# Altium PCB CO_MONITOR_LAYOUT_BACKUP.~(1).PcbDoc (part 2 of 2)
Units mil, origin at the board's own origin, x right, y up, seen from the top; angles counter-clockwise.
Board outline 3010 x 4260 mil, 2 copper layers (Top Layer, Bottom Layer), stack 62 mil thick; 120 components, 0 nets, 435 pads, 123 vias.
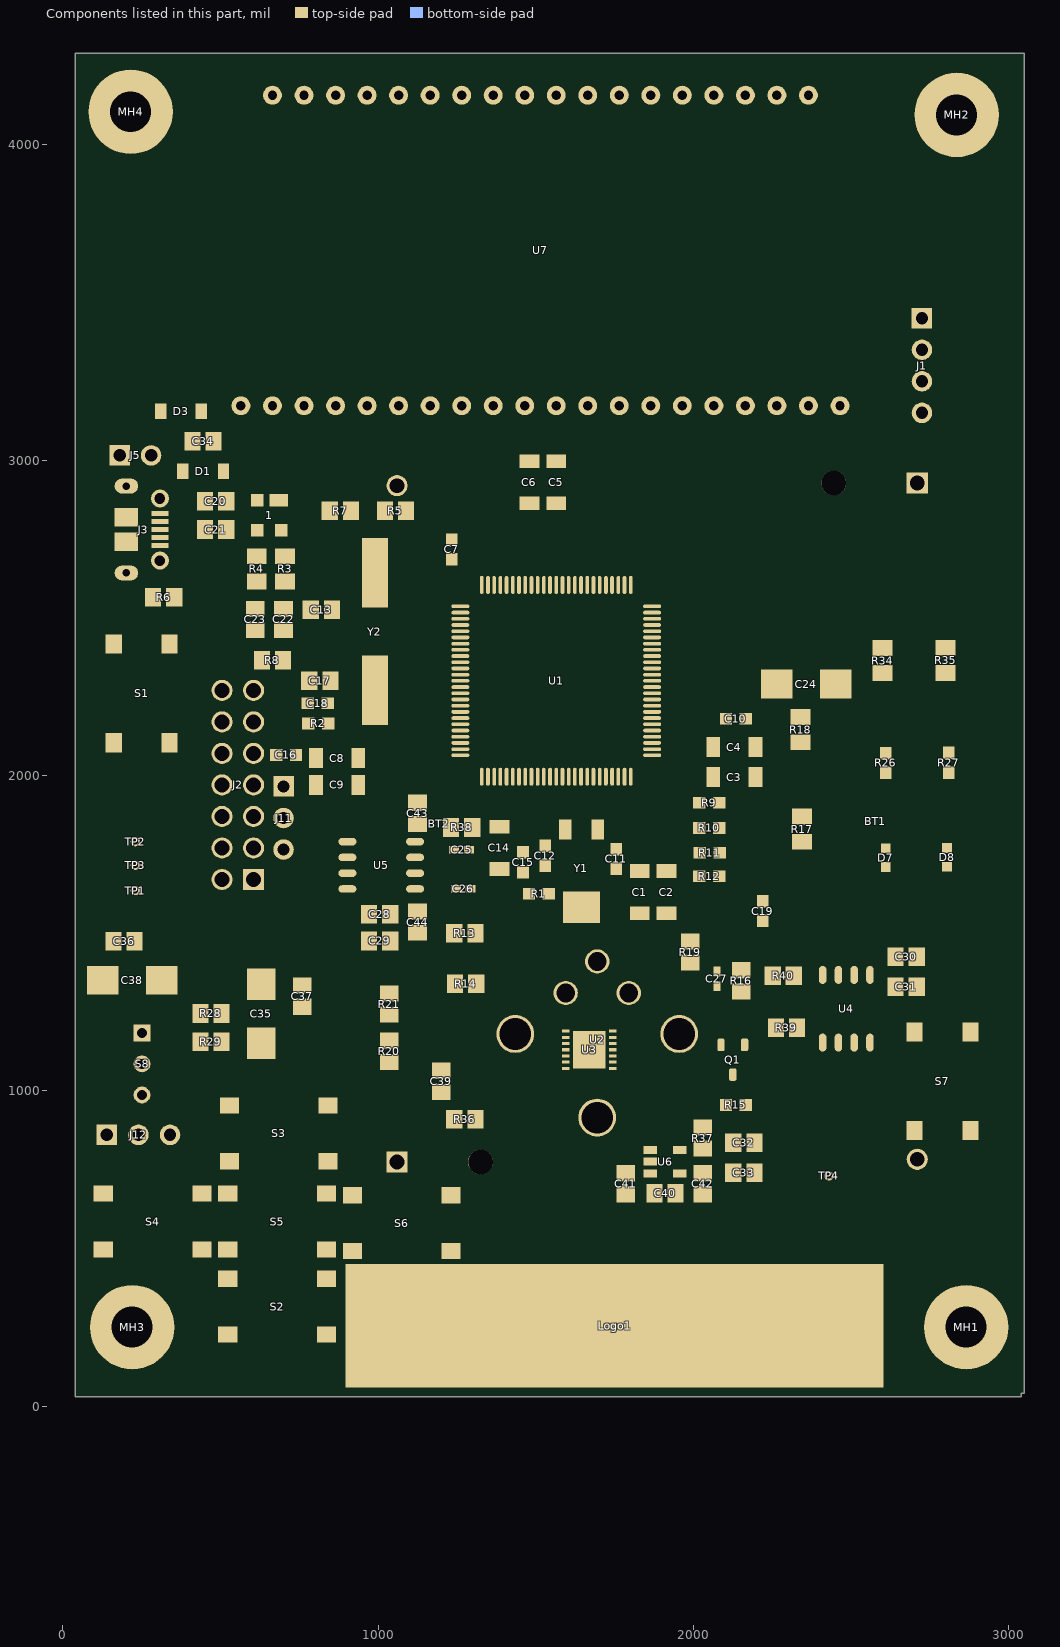
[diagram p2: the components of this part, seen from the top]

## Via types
v1: diameter 50, hole 28, Top Layer to Bottom Layer, 65 vias
v2: diameter 50, hole 28, Top Layer to Bottom Layer, tented top, 29 vias
v3: diameter 39.37, hole 19.68, Top Layer to Bottom Layer, 24 vias
v4: diameter 19.68, hole 7.87, Top Layer to Bottom Layer, tented top, 5 vias

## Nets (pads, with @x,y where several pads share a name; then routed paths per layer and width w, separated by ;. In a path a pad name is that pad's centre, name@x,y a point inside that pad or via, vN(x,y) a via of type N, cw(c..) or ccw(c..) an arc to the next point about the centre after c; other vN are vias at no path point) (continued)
copper on no net: | length 172556.5
  Top Layer w10: 105.3,4154.7 v3(128.91,4154.7) v3(301.09,4154.7) v3(301.09,4055.3) v3(128.91,4055.3) ; v3(133.91,200.3) v3(306.09,200.3) v3(306.09,299.7) v3(133.91,299.7) ; 161.42,2103.5 161.42,2416.5 226.5,2416.5 280,2470 v2(500,2470) ; v1(220,3210) 315,3210 375,3150 429.47,3150 439.47,3140 465,3140 480,3125 480,3061.54 478.46,3060 ; 227.65,1474.68 295.32,1474.68 315,1455 315,1205 293.43,1183.43 251.18,1183.43 ; 230,1477.03 230,1565 ; 230,1635 230,1565 ; 230,1790 325,1790 375,1740 375,1590 455,1510 740,1510 840,1410 840,1328.46 ; 280,3015 330,3015 355.8,3040.8 355.8,3124.2 340,3140 310.53,3140 ; 286.54,2565 279.06,2565 201.85,2642.2 ; 308.15,2681.57 296.57,2681.57 257.2,2642.2 201.85,2642.2 ; 308.15,2780 355,2780 439.44,2695.56 535,2695.56 617.2,2777.76 617.2,2697.2 615,2695 ; 308.15,2805.59 308.74,2805 355,2805 450,2710 525,2710 580,2765 580,2860 592.24,2872.24 617.2,2872.24 617.2,2842.2 655,2804.4 655,2760 680,2735 680,2700 ; 308.15,2831.18 361.18,2831.18 380.53,2850.53 380.53,2965 ; 308.15,2878.43 241.22,2878.43 201.85,2917.8 201.85,2819.37 201.85,2740.63 201.85,2642.2 ; 338.58,2103.5 338.58,2416.5 493.5,2416.5 545,2365 631.54,2365 ; 436.54,1245 436.54,1445 ; 441.5,496.42 373.58,496.42 295,575 295,685 470,860 1145,860 1160,845 1485,845 1575,755 1575,630 1610,595 2800,595 2950,745 2950,2795 2910,2835 2340,2835 2245,2740 2245,2525 2215,2495 2160,2495 2004.37,2339.37 1869.13,2339.37 ; 446.54,2870 451.54,2865 451.54,2780 ; 503.46,1245 503.46,1323.46 517.68,1337.68 629.65,1337.68 755.78,1337.68 ; 505,1770 515,1770 565,1820 645,1820 695,1770 ; 505,1970 560,1915 965,1915 980,1930 980,2010 1090,2120 1090,2185 1145.94,2240.94 1260.87,2240.94 ; 509.47,2965 509.47,2874 513.46,2870 513.46,2785 518.46,2780 555,2780 565,2790 565,2915 630,2980 745,2980 780,2945 780,2795 762.76,2777.76 692.8,2777.76 692.8,2747.2 710,2730 810,2730 870,2790 1075,2790 1110,2755 1110,2485 1137.52,2457.48 1260.87,2457.48 ; 523.5,403.58 648.58,403.58 705,460 705,505 765,565 1435,565 1485,515 2780,515 2995,730 2995,2810 2815,2990 2435,2990 2200,2755 2200,2570 2185,2555 2145,2555 1988.43,2398.43 1869.13,2398.43 ; 523.5,496.42 523.5,558.1 665,699.6 665,740 765,840 1125,840 1135,830 1480,830 1560,750 1560,610 1590,580 2805,580 2965,740 2965,2800 2915,2850 2335,2850 2230,2745 2230,2535 2210,2515 2155,2515 1999.06,2359.06 1869.13,2359.06 ; v1(525,1445) 436.54,1445 ; 565,3172.5 565,3085 600,3050 745,3050 780,3015 1085,3015 1150,2950 1255,2950 1275,2930 1275,2750 1328.78,2696.22 1328.78,2604.13 ; 605,1670 605,1610 630,1585 770,1585 795,1610 795,1865 825,1895 970,1895 1000,1925 1000,2005 1105,2110 1105,2175 1151.26,2221.26 1260.87,2221.26 ; 605,1770 550,1715 550,1605 585,1570 780,1570 810,1600 810,1855 835,1880 980,1880 1020,1920 1020,2000 1120,2100 1120,2165 1156.57,2201.57 1260.87,2201.57 ; 605,1870 585,1870 535,1820 480,1820 455,1795 455,1575 475,1555 790,1555 825,1590 825,1845 845,1865 990,1865 1040,1915 1040,1995 1135,2090 1135,2155 1161.89,2181.89 1260.87,2181.89 ; 605,1970 555,2020 475,2020 440,1985 440,1570 470,1540 800,1540 840,1580 840,1835 855,1850 1000,1850 1060,1910 1060,1990 1150,2080 1150,2145 1167.2,2162.2 1260.87,2162.2 ; 605,2170 675,2170 725,2120 870,2120 v1(905,2155) ; 615,2615 615,2533.46 613.46,2535 433.46,2535 388.46,2490 175,2490 110,2555 110,3175 220,3285 450,3285 500,3235 500,3165 542.5,3122.5 542.5,3072.5 620,2995 911.93,2995 ; 665,3172.5 665,3100 690,3075 755,3075 795,3035 1095,3035 1160,2970 1285,2970 1295,2960 1295,2760 1348.46,2706.54 1348.46,2604.13 ; 684.92,2872.24 684.92,2929.92 v2(685,2930) ; 690,2615 690,2538.46 700,2528.46 700,2535 760,2595 v2(800,2595) ; 695,1760 695,1770 ; 698.46,2365 775,2365 v2(820,2410) ; 700,1765 695,1770 ; 739.68,2065 739.68,2089.1 755.58,2105 1025,2105 1060,2140 1060,2225 1174.37,2339.37 1260.87,2339.37 ; 765,1328.46 840,1328.46 ; 765,3172.5 765,3095 805,3055 1105,3055 1170,2990 1305,2990 1315,2980 1315,2770 1368.15,2716.85 1368.15,2604.13 ; 776.54,2285 781.54,2280 ; v2(790,2665) 895,2770 1045,2770 1075,2740 1075,2485 1122.2,2437.8 1260.87,2437.8 ; 841.5,776.42 943.58,776.42 965,755 965,690 1010,645 1110,645 1130,625 1520,625 1580,565 2810,565 2980,735 2980,2805 2920,2865 2330,2865 2215,2750 2215,2545 2205,2535 2150,2535 1993.74,2378.74 1869.13,2378.74 ; 841.5,2120 841.5,2165 841.5,2228.83 ; 846.54,2840 846.54,2918.46 v2(840,2925) v2@860,2925 ; 848.46,2280 851.46,2282.99 1000,2282.99 1082.99,2282.99 1159.06,2359.06 1260.87,2359.06 ; 863.46,2525 915,2525 920,2530 920,2642.01 935,2657.01 1000,2657.01 ; 865,3172.5 865,3115 905,3075 1115,3075 1180,3010 1325,3010 1335,3000 1335,2780 1387.83,2727.17 1387.83,2604.13 ; v1(870,1970) 936.93,1970 936.93,2055 1000,2055 1075,2130 1075,2195 1160.31,2280.31 1260.87,2280.31 ; 902.72,1640 860,1640 855,1635 855,1590 885,1560 971.54,1560 971.54,1475 971.54,1385 915,1328.46 890,1328.46 ; 965,3172.5 965,3120 990,3095 1125,3095 1190,3030 1345,3030 1355,3020 1355,2790 1407.52,2737.48 1407.52,2604.13 ; v1@990,1780 v1(985,1780) 985,1810 1088.46,1913.46 1110,1913.46 ; 1000,2665 1000,2445 1066.26,2378.74 1260.87,2378.74 ; 1021.54,2840 913.46,2840 913.46,2995 1075,2995 1165,2905 1165,2650 1195,2620 1195,2535 1213.46,2516.54 1260.87,2516.54 ; 1035,1091.54 1035,922.13 ; 1035,1158.46 1035,1200 ; 1035,1241.54 1035,1200 ; 1038.46,1475 1038.46,1560 ; v1(1065,2435) 1081.89,2418.11 1260.87,2418.11 ; 1065,3172.5 1065,3135 1085,3115 1135,3115 1200,3050 1365,3050 1375,3040 1375,2800 1427.2,2747.8 1427.2,2604.13 ; 1088.46,2840 1135,2840 1145,2830 v1(1145,2590) 1180,2555 1180,2525 1208.15,2496.85 1260.87,2496.85 ; 1117.28,1640 1246.38,1640 ; 1117.28,1690 1205,1690 1241.38,1726.38 1241.38,1765 ; 1125,1913.46 1110,1913.46 ; v1(1145,2520) 1145,2490 1157.83,2477.17 1260.87,2477.17 ; v1(1165,1260) 1165,1300 1204.65,1339.65 1244.28,1339.65 ; 1165,3172.5 1165,3115 1210,3070 1385,3070 1395,3060 1395,2810 1446.89,2758.11 1446.89,2604.13 ; v1@1180,1375 v1(1180.22,1374.78) ; v1(1185,2125) 1202.52,2142.52 1260.87,2142.52 ; v2@1196.38,1735 v2(1190,1735) 1220,1705 ; 1200,996.54 1238.46,996.54 1246.73,988.27 ; 1200,1063.46 1255,1063.46 ; 1221.5,496.42 2781.42,496.42 3010,725 3010,2835 2840,3005 2430,3005 2185,2760 2185,2590 2167.5,2572.5 2137.5,2572.5 1983.11,2418.11 1869.13,2418.11 ; v2(1225,1415) 1195,1445 1195,1570 1246.38,1621.38 1246.38,1640 ; 1231.54,1835 1231.54,1886.54 1248.46,1903.46 1265,1903.46 1298.46,1903.46 1328.78,1933.78 1328.78,1995.87 ; v1(1235,2610) 1235,2685.44 ; 1241.54,910 1255,923.46 1255,980 1246.73,988.27 ; 1260.87,2063.78 1193.78,2063.78 1180,2050 1180,1775 1145,1740 1117.28,1740 1027.41,1740 1005,1717.59 1005,1645 1020,1630 1065,1630 1085,1610 1115,1610 1125,1600 1125,1568.46 1166.54,1568.46 1174.8,1560.2 1174.8,1419.8 1105,1350 v1(1105,1200) 1035,1200 ; 1260.87,2083.46 1183.46,2083.46 1160,2060 1160,1995 1125,1995 1110,1980 1110,1913.46 ; 1260.87,2122.83 1357.83,2122.83 1405,2170 v1@1632.18,2170 ; 1260.87,2319.68 1309.68,2319.68 v1(1350,2360) ; 1260.87,2398.43 1483.72,2398.43 1735,2147.15 1735,2065 1710,2040 1565,2040 1565,1995.87 1565,1885 v2(1535,1855) ; 1265,3172.5 1265,3120 1295,3090 1395,3090 1415,3070 1415,2820 1466.57,2768.43 1466.57,2604.13 ; v1(1280,1015) 1253.27,988.27 1246.73,988.27 ; 1293.62,1640 1293.62,1618.62 1241.54,1566.54 1241.54,1500 1241.54,1449.05 1311.21,1379.37 1311.21,1339.65 ; 1298.46,1835 1288.62,1825.16 1288.62,1765 1288.62,1728.62 1246.38,1686.38 1246.38,1640 ; v2(1300,1690) 1341.81,1690 ; 1308.46,910 1325,926.54 1325,1035 1296.54,1063.46 1255,1063.46 ; 1308.46,1500 1308.46,1563.46 1341.81,1596.81 1341.81,1690 ; v2(1320,1215) 1355,1180 1435,1180 1435,1105 1490,1050 ; v2(1332.13,1432.13) 1437.87,1432.13 1500,1370 1569.42,1370 1599.42,1400 v1(1605,1400) 1605,1437.32 1632.68,1465 1789.67,1465 1955,1299.67 1955,1180 ; 1348.46,1995.87 1348.46,1931.65 1341.81,1925 1341.81,1690 ; 1365,3172.5 1365,3150 1435,3080 1435,2821.96 1486.26,2770.7 1486.26,2604.13 ; 1385,1836.93 1456.93,1836.93 ; 1407.52,1995.87 1407.52,2052.52 1485,2130 v1(1580,2130) ; v2(1427.2,1922.2) 1427.2,1995.87 ; 1460,1756.5 1460,1895 1486.26,1921.26 1486.26,1995.87 ; 1465,3172.5 1625,3012.5 1625,2835 1584.68,2794.69 1584.68,2604.13 ; v1(1470,1515) 1492.13,1492.87 1763.31,1492.87 1763.9,1493.46 1870,1493.46 1885,1478.46 1985,1478.46 ; v1@1480,2920 1480,2863.07 1565,2863.07 1545.31,2843.39 1545.31,2604.13 ; v1(1480,3085) 1480,2996.93 1565,2996.93 ; v1(1500,1095) 1534.68,1095 1550,1110.32 1595.2,1110.32 ; 1505.94,2604.13 1505.94,2504.06 v1(1740,2270) ; v1(1510,1285) 1510,1235 1530,1215 1530,1184.94 1565.26,1149.68 1595.2,1149.68 ; 1525,1776.5 1581.5,1776.5 1593.82,1788.82 1593.82,1828.03 1593.82,1896.18 1585,1905 1585,1995.55 1584.68,1995.87 ; 1525.63,2604.13 1525.63,2544.37 1775,2295 v1(1775,2190) ; 1541.5,1625 1541.5,1653.5 1524.85,1670.15 1504.85,1670.15 1500,1675 1500,1880 1545.31,1925.31 1545.31,1995.87 ; 1565,3172.5 1645,3092.5 1645,2830 1604.37,2789.37 1604.37,2604.13 ; v1(1580,980) 1580,945 1605,920 1645,920 ; 1595.2,1070.94 1575.94,1070.94 1565,1060 1565,1045 1572.21,1037.79 1657.59,1037.79 v1(1667.79,1027.59) ; 1595.2,1090.63 1565.63,1090.63 1525,1050 1490,1050 ; 1595.2,1130 1560.43,1130 1515,1175.43 1515,1205 1450,1270 1295,1270 1265,1240 1265,1160.15 1615.15,810 1735,810 1810,885 1880,885 1950,955 2040,955 2080,915 2080,825 2071.54,816.54 2030,816.54 2030,738.46 ; 1595.2,1169.37 1567.91,1169.37 1545,1192.28 1545,1305 1529.61,1320.39 1529.23,1320 1415,1320 1385,1290 1285,1290 1230,1235 1230,1150 1255,1125 1255,1063.46 ; 1595.2,1189.06 1570,1189.06 1560,1199.06 1560,1240 1582.13,1262.13 1647.13,1262.13 v1(1790,1405) ; 1604.37,1995.87 1604.37,1935.63 1630,1910 1660,1910 1696.18,1873.82 1696.18,1828.03 1696.18,1778.82 1708.5,1766.5 1770,1766.5 ; 1624.06,1995.87 1624.06,1945.94 1640,1930 1695,1930 1830,1795 1830,1695 1905,1695 1920,1680 ; 1624.06,2604.13 1624.06,2779.06 1665,2820 1665,3172.5 ; v1(1632.18,2095) v1(1632.18,2168.51) ; 1643.74,1995.87 1643.74,1956.26 1655,1945 1710,1945 1860,1795 1925,1795 1980,1740 1980,1650 2003.69,1626.31 2133.69,1626.31 2158.5,1601.5 2220,1601.5 ; 1643.74,2604.13 1643.74,2768.74 1685,2810 1685,3030 1765,3110 1765,3172.5 ; 1663.43,2604.13 1663.43,2758.43 1705,2800 1705,3005 1735,3035 1790,3035 1865,3110 1865,3172.5 ; 1683.11,2604.13 1683.11,2748.11 1725,2790 1725,2995 1745,3015 1870,3015 1965,3110 1965,3172.5 ; 1685,915 1870,915 2087.6,1132.6 2087.6,1145.71 2087.6,1177.6 2110,1200 2110,1230 1990,1350 1990,1406.54 ; v2(1695,1700) 1695,1703.5 1755,1703.5 ; 1702.8,2604.13 1702.8,2737.8 1745,2780 1745,2975 1765,2995 1945,2995 2065,3115 2065,3172.5 ; 1722.48,2604.13 1722.48,2727.48 1765,2770 1765,2955 1785,2975 2025,2975 2165,3115 2165,3172.5 ; 1742.17,1995.87 1742.17,1947.83 1815,1875 1945,1875 1955,1865 1955,1787.15 1987.15,1755 2020,1755 2020,1730 2030,1720 2070,1720 2081.5,1708.5 2081.5,1680 ; 1742.17,2604.13 1742.17,2717.17 1785,2760 1785,2940 1800,2955 2105,2955 2265,3115 2265,3172.5 ; 1744.8,1070.94 1810,1070.94 1840,1040.94 v1(1840,1030) ; 1744.8,1090.63 1879.37,1090.63 1895,1075 v1(1935,1075) ; 1744.8,1110.32 2010.32,1110.32 2055,1155 v1(2055,1215) ; 1744.8,1130 1790,1130 1825,1165 1825,1245 1855,1275 v1(1895,1275) ; 1744.8,1169.37 1784.37,1169.37 1790,1175 1790,1220 1775,1235 v2(1780,1235) ; 1761.85,2604.13 1761.85,2706.85 1805,2750 1805,2925 1815,2935 2185,2935 2365,3115 2365,3172.5 ; v1(1780,970) 1765,985 1645,985 1615,1015 1525,1015 1490,1050 ; 1781.54,1995.87 1781.54,1948.46 1835,1895 1955,1895 1975,1875 1975,1805 1985,1795 2082.99,1795 ; 1781.54,2604.13 1781.54,2696.54 1825,2740 1825,2900 1840,2915 2260,2915 2465,3120 2465,3172.5 ; 1795,671.54 1798.46,675 ; 1795,738.46 1795,795 1812.4,812.4 1862.76,812.4 ; 1801.22,1995.87 1801.22,1953.78 1841.5,1913.5 2018.5,1913.5 2018.5,1833.5 ; 1801.22,2604.13 1801.22,2696.22 v1(1877.5,2772.5) ; v1(1860,2595) 1860,2630 1855,2635 1880,2660 v1(1990,2660) ; 1862.76,737.6 1957.24,737.6 1957.24,688.78 1943.46,675 1945,610 ; 1869.13,2063.78 1988.78,2063.78 2015,2090 2063.07,2090 2063.07,1995 v2(1970,1995) ; 1869.13,2103.15 1870.98,2105 1990,2105 2065,2180 2103.5,2180 ; 1869.13,2122.83 1982.83,2122.83 2150,2290 2264.8,2290 2264.8,2199.8 2245,2180 2245,1925 2233.5,1913.5 2081.5,1913.5 ; 1869.13,2142.52 1982.52,2142.52 2205,2365 2460,2365 2490,2395 2490,2585 2590,2685 v1(2590,2750) ; 1869.13,2162.2 1982.2,2162.2 2200,2380 2390,2380 2459.23,2449.23 v1(2459.23,2750) ; 1869.13,2181.89 1981.89,2181.89 2195,2395 2355,2395 2405,2445 v1(2405,2710) ; 1869.13,2201.57 1981.57,2201.57 2190,2410 2295,2410 2345,2460 v1(2345,2685) ; 1869.13,2221.26 1981.26,2221.26 2190,2430 2275,2430 2290,2445 2290,2725 2355,2790 2635,2790 2665,2760 2665,2690 2600,2625 2600,2404.53 ; 1869.13,2240.94 1975.94,2240.94 2180,2445 2260,2445 2275,2460 2275,2730 2350,2805 2740,2805 2800,2745 2800,2405 ; 1869.13,2300 1925,2300 v1(1950,2275) ; 1869.13,2319.68 2009.68,2319.68 2165,2475 2215,2475 2260,2520 2260,2735 2345,2820 2905,2820 2935,2790 2935,1475 2885,1425 ; 1869.13,2437.8 1977.8,2437.8 2135,2595 2155,2595 2170,2610 2170,2770 2220,2820 v1(2220,2875) ; 1869.13,2457.48 1967.48,2457.48 2120,2610 2135,2610 2150,2625 2150,2780 2165,2795 v1(2165,2835) ; 1869.13,2477.17 1962.17,2477.17 2130,2645 2130,2785 2110,2805 v1(2110,2875) ; 1869.13,2496.85 1956.85,2496.85 2115,2655 2115,2775 2060,2830 v1(2060,2835) ; 1869.13,2516.54 1946.54,2516.54 2085,2655 2085,2745 2060,2770 v1(2010,2770) ; 1869.13,2536.22 1936.22,2536.22 2055,2655 2055,2710 2035,2730 1985,2730 v1(1945,2770) ; 1915,1696.93 1915,1675 1985,1605 2125,1605 2180,1550 2180,1520 2200,1500 2410,1500 ; 1957.24,812.4 1957.24,867.24 1973.46,883.46 2025,883.46 ; 1990,1473.46 2051.54,1473.46 2070,1455 2070,1435 2040,1405 2040,1340 2048.62,1331.38 2074.84,1331.38 2135.16,1331.38 2151.5,1315.04 2151.5,1263.5 2190,1225 2190,1110 2240,1060 2440,1060 2460,1080 2460,1152.72 ; 1995,1406.54 1995,1426.54 ; v1(1995,1550) 2030,1550 2115,1465 2270,1465 2318.46,1416.54 2318.46,1365 ; v2(2060,1050) 2061.22,1051.22 2125,1051.22 ; 2074.84,1378.62 2148.15,1378.62 ; 2081.5,1833.5 2082.99,1832.01 2082.99,1795 ; 2082.99,1755 2082.99,1795 ; 2101.54,955 2101.54,971.97 ; 2103.5,955 2103.5,911.5 2126.54,888.46 2126.54,835 2126.54,740 2126.54,611.54 2125,610 ; v2(2115,1560) 2115,1515 2150,1480 2360,1480 2380,1460 2380,1315 2328.46,1263.46 2328.46,1200 ; v2(2145,1720) v2(2205,1780) ; 2151.5,970 2162.4,980.91 2162.4,1145.71 ; 2151.5,1381.97 2168.46,1365 2251.54,1365 ; 2220,1538.5 2293.5,1538.5 v2(2295,1540) ; 2256.54,1195 2256.54,1128.46 2300,1085 2390,1085 2410,1105 2410,1152.72 ; 2261.54,1200 2261.54,1355 ; v1(2290,1940) 2340,1940 ; v2(2290,2030) 2280,2040 2280,2160 2300,2180 2340,2180 ; v2(2335,1715) 2345,1725 2345,1790 ; 2340,1875 2340,1940 ; 2340,2100 2340,1940 ; v2(2345,805) 2345,1020 2365,1040 2485,1040 2510,1065 2510,1152.72 ; 2410,1367.28 2410,1500 ; v1(2480,890) 2590,890 ; 2600,2324.53 2600,2204.53 2610,2194.53 2610,2071.02 ; 2610,1769.06 2610,2008.03 ; v3(2778.91,200.3) 2815.3,200.3 v3(2865,150.59) 2914.7,200.3 v3(2951.09,200.3) v3(2951.09,299.7) 2914.7,299.7 v3(2865,349.41) 2828.61,349.41 v3(2778.91,299.7) ; 2800,2325 2800,2205 2810,2195 2810,2071.5 ; 2805,1769.53 2810,1769.53 2810,2008.5 ; v3(2835,3995.59) 2785.3,4045.3 v3(2748.91,4045.3) v3(2748.91,4144.7) 2785.3,4144.7 v3(2835,4194.41) 2884.7,4144.7 v3(2921.09,4144.7) v3(2921.09,4045.3) ; 2883.58,1211.5 2883.58,1423.58 ; 230,1565 355,1565 436.54,1483.46 436.54,1445 ; 840,1328.46 890,1328.46 ; 890,1328.46 890,1045 1012.87,922.13 1035,922.13 ; 1035,922.13 1135,922.13 1197.13,860 1495,860 1590,765 1590,655 1635,610 1945,610 ; 1945,610 2125,610 ; 2125,610 2523.84,610 2590,676.16 2590,890 ; 2410,1500 2685,1500 2708.46,1476.54 2708.46,1425 2708.46,1330 2708.46,1273.46 2690,1255 2655,1255 2590,1190 2590,890
  Bottom Layer w10: 180,3015 125,3015 100,2990 100,1945 140,1905 140,1820 ; v3(215,4005.59) 215,4105 ; 220,250 435,250 v1(440,245) ; v1(220,3210) 275,3210 500,2985 500,2510 ; 251.18,1085 140,1085 ; v1(375,3235) v1(375,3355) ; v2(500,2470) 500,2510 ; 505,1670 505,1600 540,1565 740,1565 790,1615 790,1925 750,1965 700,1965 ; v1(525,1445) 710,1445 870,1605 v1(870,1970) 870,2065 830,2105 830,2180 875,2225 1020,2225 1340,2545 1340,2845 1420,2925 v1(1475,2925) 1615,2925 1970,2570 1970,2330 2000,2300 2000,2240 1970,2210 v2(1970,1995) 2025,1940 v1(2290,1940) ; 665,4157.5 665,4085 1420,3330 1540,3330 1615,3255 1615,3120 1877.5,2857.5 v1(1877.5,2772.5) v1@1860,2755 ; 700,1865 655,1820 140,1820 ; 765,4157.5 765,4085 1495,3355 1615,3355 1715,3255 1715,3105 1945,2875 v1(1945,2770) ; v2(790,2665) 655,2665 500,2510 ; v2(800,2595) 800,2605 920,2725 1140,2725 1185,2680 1185,2565 1145,2525 v1(1145,2520) ; v2(820,2410) 820,2540 975,2695 1115,2695 1145,2665 v1(1145,2590) ; v2@835,2930 v2(840,2925) ; v1(840,1085) v2(945,1085) ; 865,4157.5 865,4085 1575,3375 1695,3375 1815,3255 1815,3095 2010,2900 v1(2010,2770) ; v1(905,2155) 935,2125 v1(1185,2125) ; 965,4157.5 965,4070 1635,3400 1775,3400 1925,3250 1925,3050 2060,2915 v1(2060,2835) ; v1(985,1780) 985,1515 1105,1395 v1(1105,1200) 1105,1065 1520,650 2190,650 v2(2345,805) ; 1060,774.09 225.91,774.09 140,860 140,1085 ; 1060,2918.98 1136.02,2995 1590,2995 1990,2595 2575,2595 2710,2730 2710,2927.44 ; v1(1065,2435) 1065,2460 1080,2475 1160,2475 1195,2510 1195,2540 1235,2580 v1(1235,2610) ; 1065,4157.5 1065,4070 1710,3425 1855,3425 2015,3265 2015,3050 2110,2955 v1(2110,2875) ; v2(1130,1425) v1(1180.22,1374.78) v1@1414.78,1374.78 ; v1(1165,1260) 1210,1215 v2(1320,1215) ; 1165,4157.5 1165,4055 1770,3450 1935,3450 2115,3270 2115,3090 2165,3040 v1(2165,2835) ; v2(1190,1735) 1235,1690 v2(1300,1690) ; v2(1225,1415) 1315,1415 v2(1332.13,1432.13) ; 1265,4157.5 1265,4050 1840,3475 2060,3475 2220,3315 v1(2220,2875) ; v1(1280,1015) 1405,1015 1430,1040 1430,1075 1357.55,1147.45 1357.55,1222.55 1400,1265 1450,1265 1470,1285 v1(1510,1285) ; v1(1350,2360) 1585,2595 v1(1860,2595) ; v1(1405,950) v1(1470,1015) ; v1(1415,1375) v2(1415,1570) ; v2(1427.2,1922.2) 1427.2,1817.8 1470,1775 v1(1470,1515) ; v1(1495,2315) v1(1565,2385) ; v1(1500,1095) 1500,1050 1525,1025 1525,1000 1545,980 v1(1580,980) ; v1(1530,1420) 1530,1850 v2(1535,1855) ; v1(1580,2130) 1650,2130 2115,1665 v2(2115,1560) ; v1(1605,1400) 1605,1375 1645,1335 1645,1275 1625,1255 1610,1255 1590,1235 1590,1075 1637.41,1027.59 v1(1667.79,1027.59) ; v4(1630.63,1130) v4(1670,1130) ; v1(1632.18,2095) 1632.18,2077.82 1790,1920 v1(1790,1405) 1870,1405 1905,1440 1905,1520 1935,1550 v1(1995,1550) ; v4(1670,1082.76) v4(1670,1130) ; v4(1670,1177.24) v4(1670,1130) ; v1(1700,705) 2215,705 2275,765 v2(2275,785) ; v1(1740,2270) 1785,2270 1822.5,2232.5 1822.5,2032.5 1925,1930 1990,1930 2222.5,1697.5 ; v1(1775,2190) 1775,2040 2120,1695 ; v1(1780,970) 1940,970 2020,1050 v2(2060,1050) ; v2(1780,1235) 1775,1235 1805,1205 1805,1150 1845,1110 2052.5,1110 2177.5,985 2385,985 v1(2480,890) ; v1(1840,1030) 1809.37,1030 v4(1709.37,1130) v4(1670,1130) ; v1(1895,1275) 2145,1275 2180,1310 2180,1635 2120,1695 ; v1(1935,1075) 1850,1075 1710,1215 1710,1305 1645,1370 1645,1497.82 1702.18,1555 1702.18,1597.18 1745,1640 1745,1825 1525,2045 1525,2215 1645,2335 1785,2335 1845,2275 v1(1950,2275) ; 1970,2535 2690,2535 2800,2645 2800,3430 2780,3450 2725,3450 ; v1(1990,2660) 1992.13,2657.87 2252.13,2657.87 2285,2625 2550,2625 2650,2725 2650,2795 2625,2820 2625,3330 2645,3350 2725,3350 ; v1(2055,1215) 2150,1215 2195,1260 2195,1670 2240,1715 v2(2335,1715) ; 2065,4157.5 2065,4070 2317.68,3817.32 2317.68,3127.32 2345,3100 v1(2345,2685) ; v2(2145,1720) 2120,1695 ; 2165,4157.5 2165,4070 2415,3820 2415,3145 2395,3125 2395,3000 2365,2970 2365,2855 2405,2815 v1(2405,2710) ; v2(2205,1780) 2335,1910 2335,1985 v2(2290,2030) ; 2265,4157.5 2265,4075 2515,3825 2515,2885 2459.23,2829.23 v1(2459.23,2750) ; v2(2295,1540) 2400,1435 v1(2530,1435) ; 2365,4157.5 2365,4075 2540,3900 2540,3170 2590,3120 v1(2590,2750) ; 140,1085 140,1820
  other v1: 1400,690 975,2955
  other v2: 1470,770
  other v3: 220,150.59 220,349.41 215,4204.41

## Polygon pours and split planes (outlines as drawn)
no net on Top Layer "Bottom Layer-No Net" (solid, pour order 8): 50,4275 3030,4275 3030,2165 3030,1110 3030,320.02 3030,185 3030,120 3030,85 3030,55 3030,45 50,45
no net on Top Layer "Bottom Layer-No Net" (solid, pour order 12): 360,4265 360,3935 150,3935 55,3935 55,3905 55,410 360,410 385,410 385,75 2710,75 2710,410 3030,410 3030,3935 2685,3935 2685,4045 2685,4265
no net on Top Layer "Bottom Layer-No Net" (solid, pour order 10): 855,1415 475,1415 475,1005 895,1005 990,910 990,861.88 1285,861.88 1508.12,861.88 1565,805 1565,620 2610,620 2610,1255 2915,1255 2915,1510 2610,1510 2340,1510 2340,1620 2245,1620 1505,1620 1505,1788.82 1593.82,1788.82 1593.82,2090 1150,2090 855,1795
no net on Bottom Layer "Bottom Layer-No Net" (solid, pour order 14): 50,4275 360,4275 3030,4275 3030,3935 3030,410 3030,45 50,45 50,410

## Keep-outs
Keep-Out Layer:
  text ".Layer_Name" at 577,-858.49 h60

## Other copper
Top Layer:
  text ".Layer_Name" at 577,-858.49 h60
Bottom Layer:
  text ".Layer_Name" at 577,-858.49 h60

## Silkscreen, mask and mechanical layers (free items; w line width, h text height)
Top Overlay:
  text ".Layer_Name" at 577,-858.49 h60
Bottom Overlay:
  text ".Layer_Name" at 577,-858.49 h60
Top Paste:
  text ".Layer_Name" at 577,-858.49 h60
Bottom Paste:
  text ".Layer_Name" at 577,-858.49 h60
Top Solder:
  text ".Layer_Name" at 577,-858.49 h60
  text ".Layer_Name" at 577,-858.49 h60
Bottom Solder:
  text ".Layer_Name" at 577,-858.49 h60
Drill Guide:
  text ".Layer_Name" at 577,-858.49 h60
M1 Board Outline:
  lines w47.24: 50,45 50,4275 3030,4275 3030,45 50,45
  text ".Layer_Name" at 577,-858.49 h60
M2 Board Dimensions:
  rectangle: 0,-275 125,-150
  rectangle: 125,-400 500,-275
  lines w7: 0,-275 1000,-275 ; 125,-400 125,-150 ; 250,-400 250,-150 ; 500,-400 500,-150 ; 750,-400 750,-150 ; 0,-400 1000,-400 1000,-150 0,-150 0,-400
  text ".Layer_Name" at 577,-858.49 h60
M3 3D STEP Top:
  text ".Layer_Name" at 577,-858.49 h60
M4 3D STEP Bottom:
  text ".Layer_Name" at 577,-858.49 h60
M5 Assembly Top:
  lines w10: -292,-930.17 6308,-930.17 ; -292,-726.83 6310,-726.83 ; -292,-523.5 -292,-1133.5 3713,-1133.5 6310,-1133.5 6310,-523.5 -291.5,-523.5 -291.5,-1133.5 1284,-1133.5 ; 2173,-1133.5 2173,-523.5 ; 3440,-726.83 3440,-523.5 ; 4280,-726.83 4280,-523.5 ; 4902,-1140 4902,-937.17
  text "COMPONENTS MARKED 'DNP' SHOULD NOT BE POPULATED." at 1153.5,-318.5 h60
  text "ASSEMBLY VARIANT:" at 1153,-434 h60
  text ".VariantName" at 2189,-434 h60
  text "PCB VIEWED FROM TOP SIDE" at -228.5,-655.67 h60
  text "BOARD #:" at 2248,-655.67 h60
  text ".PRJ_Number" at 2793.5,-655.67 h60
  text "REV:" at 3638,-655.67 h60
  text ".PCB_Rev" at 3929.5,-655.67 h60
  text "SVN REV:" at 4476,-655.67 h60
  text ".VersionControl_RevNumber" at 4982,-655.67 h60
  text "TID #:" at 2248,-859 h60
  text ".TID" at 2793.5,-859 h60
  text "PLOT NAME =" at -228.5,-1064.34 h60
  text ".plot_File_Name" at 577,-1064.34 h60
  text "GENERATED    :" at 2250,-1064.34 h60
  text ".Print_Date" at 3119.5,-1064.34 h60
  text ".Print_Time" at 3848.5,-1064.34 h60
  text "TEXAS INSTRUMENTS" at 5113,-1064.34 h60
M6 Assembly Bottom:
  lines w10: -292.5,-727.33 6309.5,-727.33 ; -290.5,-930.67 6309.5,-930.67 ; 1115.5,-1140.5 1115.5,-937.67 ; 1737.5,-727.33 1737.5,-524 ; 2577.5,-727.33 2577.5,-524 ; 3844.5,-1134 3844.5,-524 ; 4733.5,-1134 6309,-1134 6309,-524 -292.5,-524 -292.5,-1134 2304.5,-1134 6309.5,-1134 6309.5,-524
  text "COMPONENTS MARKED 'DNP' SHOULD NOT BE POPULATED." at 6102,-318 h60
  text ".VariantName" at 5058,-434 h60
  text "ASSEMBLY VARIANT:" at 6097,-434 h60
  text ".VersionControl_RevNumber" at 1035.5,-656.17 h60
  text "SVN REV:" at 1541.5,-656.17 h60
  text ".PCB_Rev" at 2088,-656.17 h60
  text "REV:" at 2379.5,-656.17 h60
  text ".PRJ_Number" at 3224,-656.17 h60
  text "BOARD #:" at 3769.5,-656.17 h60
  text "PCB VIEWED FROM BOTTOM SIDE" at 6246,-656.17 h60
  text ".TID" at 3224,-859.5 h60
  text "TID #:" at 3769.5,-859.5 h60
  text "TEXAS INSTRUMENTS" at 904.5,-1064.84 h60
  text ".Print_Time" at 2169,-1064.84 h60
  text ".Print_Date" at 2898,-1064.84 h60
  text "GENERATED    :" at 3767.5,-1064.84 h60
  text ".plot_File_Name" at 5440.5,-1064.84 h60
  text "PLOT NAME =" at 6246,-1064.84 h60
M9 Title Sheet:
  drawing of 57 lines, arcs and shapes, not listed
  text "1" at 739.84,8036.5 h70
  text "2" at 3235.5,8036.5 h70
  text "3" at 5724.84,8036.5 h70
  text "4" at 8231.51,8036.5 h70
  text "5" at 10730.5,8036.5 h70
  text "6" at 13235.5,8036.5 h70
  text "A" at -416.5,6893.5 h70
  text "A" at 14383.5,6893.5 h70
  text "B" at -416.5,4513.5 h70
  text "B" at 14383.5,4513.5 h70
  text "C" at -416.5,2138.5 h70
  text "C" at 14383.5,2138.5 h70
  text "PROJECT TITLE:" at 11343.5,277.5 h45
  text ".PRJ_Title" at 11393.5,144.17 h70
  text "DESIGNED FOR:" at 11343.5,-23.5 h45
  text ".PRJ_Customer" at 11393.5,-163.5 h70
  text "D" at -416.5,-231.5 h70
  text "D" at 14383.5,-231.5 h70
  text "FILE NAME:" at 11343.5,-323.5 h45
  text ".PCB_File_Name_No_Path" at 11393.5,-443.5 h70
  text "Texas Instruments (TI) and/or its licensors do not warrant the accuracy or completeness of this specification" at 6374,-605.34 h45
  text "ENGINEER:" at 11343.5,-613.5 h45
  text "LAYOUT BY:" at 12848.5,-613.5 h45
  text "or any information contained therein. TI and/or its licensors do not warrant that this design will meet" at 6329.01,-718 h45
  text ".PRJ_Engineer" at 11393.5,-768.49 h70
  text ".PCB_Layout" at 12899,-768.49 h70
  text "the specifications, will be suitable for your application or fit for any particular purpose, or will operate in" at 6329.01,-830.67 h45
  text ".Layer_Name" at 577,-858.49 h60
  text "ALTIUM DESIGNER VERSION:" at 12848.5,-923.5 h45
  text "an implementation. TI and/or its licensors do not warrant that the design is production worthy. You should" at 6329.01,-943.33 h45
  text "completely validate and test your design implementation to confirm the system functionality for your application." at 6374,-1056 h45
  text ".print_Scale" at 11393.5,-1056.83 h70
  text ".Application_BuildNumber" at 12899,-1056.83 h70
  text "1" at 739.84,-1263.5 h70
  text "2" at 3235.5,-1263.5 h70
  text "3" at 5724.84,-1263.5 h70
  text "4" at 8231.51,-1263.5 h70
  text "5" at 10730.5,-1263.5 h70
  text "6" at 13235.5,-1263.5 h70
M10 Fab Notes:
  drawing of 173 lines, arcs and shapes, not listed
  text "DESIGN INFORMATION" at 12378.02,6201 h60
  text "MIN. TRACK WIDTH:" at 11733.46,6021 h60
  text "8" at 12829.7,6021 h60
  text "MIL" at 12984.46,6021 h60
  text "MIN. CLEARANCE:" at 11733.46,5889 h60
  text "0.2" at 12769.7,5889 h60
  text "mm" at 12984.46,5889 h60
  text "MIN. VIA PAD SIZE:" at 11733.46,5757 h60
  text "24" at 12799.71,5757 h60
  text "MIL" at 12984.46,5757 h60
  text "0.05mm (2MIL)" at 12428.46,5615.29 h60
  text "MINIMUM ANNULAR RING" at 11404.23,5611 h60
  text "EXTERNAL" at 13136.46,5611 h60
  text "PER" at 11604.23,5493 h60
  text "IPC-D-275 CLASS 2 LEVEL C" at 11824.23,5493 h60
  text "MIL, HOLES" at 13312.46,5380.71 h60
  text "+/-" at 12920,5380 h60
  text "+/-" at 13774,5380 h60
  text "REGISTRATION TOLERANCES:" at 11404.23,5375 h60
  text "METAL" at 12604,5375 h60
  text "5" at 13180.2,5375 h60
  text "3" at 14013.2,5375 h60
  text "MIL" at 14129.46,5375 h60
  text "+/-" at 13774,5262 h60
  text "HOLE SIZE TOLERANCE (UNLESS OTHERWISE SPECIFIED):" at 11404.23,5257 h60
  text "3" at 14013.2,5257 h60
  text "MIL" at 14129.46,5257 h60
  text "MATERIAL:" at 11329.46,5047.54 h60
  text "FR-4 High Tg" at 12315.9,4907.21 h60
  text "FR-408" at 11750.46,4898.64 h60
  text "OTHER" at 13238.46,4898.64 h60
  text "X" at 12161,4895 h60
  text "62 MIL (1.6mm) +/-10%" at 12070.56,4735.92 h60
  text "THICKNESS:" at 11404.23,4731.64 h60
  text "X" at 11942.4,4731.64 h60
  text "OTHER" at 13355.46,4731.64 h60
  text "TOLERANCE:" at 11404.23,4573.64 h60
  text "X" at 12243.53,4573.64 h60
  text "ANSI IPC-6012 TYPE 3 CLASS 2" at 12430.48,4573.64 h60
  text "OTHER +/-" at 12430.46,4417.64 h60
  text "BOW & TWIST:" at 11404.23,4260.64 h60
  text "X" at 12243.53,4260.64 h60
  text "ANSI IPC-6012 TYPE 3 CLASS 2" at 12430.48,4260.64 h60
  text "OTHER +/-" at 12430.46,4102.13 h60
  text "DRILLING:" at 11329.46,3963.64 h60
  text "REFERENCE:" at 11404.23,3846.64 h60
  text "X" at 12052.46,3846.64 h60
  text "AS SHOWN" at 12239.46,3846.64 h60
  text "X" at 12953.46,3846.64 h60
  text "NC_DRILL FILES" at 13090.46,3846.64 h60
  text "PTH COPPER THICKNESS:" at 11404.23,3688.64 h60
  text "X" at 12534.46,3688.64 h60
  text "20-30 um" at 12671.46,3688.64 h60
  text "OTHER" at 13388.46,3688.64 h60
  text "BOARD FINISH:" at 11329.46,3529.64 h60
  text "SILKSCREEN:" at 11484.68,3411.64 h60
  text "X" at 12433.46,3411.64 h60
  text "TOP" at 12559.46,3411.64 h60
  text "X" at 12943.46,3411.64 h60
  text "BOTTOM" at 13070.46,3411.64 h60
  text "SILKSCREEN COLOR:" at 11484.68,3244.64 h60
  text "X" at 12432.42,3244.64 h60
  text "WHITE" at 12559.46,3244.64 h60
  text "OTHER" at 13070.46,3244.64 h60
  text "X" at 12563.42,3085.44 h60
  text "GREEN" at 12690.46,3085.44 h60
  text "OTHER" at 13308.46,3085.44 h60
  text "SOLDER RESIST COLOR:" at 11484.68,3074.64 h60
  text "X" at 12563.42,2915.44 h60
  text "MATTE" at 12690.46,2915.44 h60
  text "SEMI-GLOSS" at 13308,2914.8 h60
  text "IMMERSION GOLD (ENIG)" at 12390.46,2726.92 h60
  text "ENEPIG" at 13728,2723.64 h60
  text "SURFACE FINISH:" at 11329.46,2722.64 h60
  text "X" at 12203.51,2722.64 h60
  text "IMM. TIN/SILVER OR EQUIV" at 11659,2565.64 h60
  text "OTHER" at 13090.46,2565.64 h60
  text "ARRAY/PANEL:" at 11329.46,2386.64 h60
  text "CUT AND TRIM PER M1 BOARD OUTLINE" at 12390.46,2382.35 h60
  text "N.C. ROUTE" at 12390.46,2230.64 h60
  text "X" at 13069.46,2230.64 h60
  text "V. SCORE" at 13256.46,2230.64 h60
  text "CERTIFICATION:" at 11329.46,2093.64 h60
  text "MATERIALS AND WORKMANSHIP FOR ALL PCBS" at 12054.46,2093.64 h60
  text "TO MEET OR EXCEED THE REQUIREMENTS OF:" at 12054.46,1995.64 h60
  text "X" at 11680.96,1859.13 h60
  text "ANSI IPC-A-600F CLASS ->" at 11819.96,1859.13 h60
  text "X" at 13459.02,1859.13 h60
  text "2" at 13577.96,1859.14 h60
  text "1" at 13262.96,1857.64 h60
  text "3" at 13931.96,1857.64 h60
  text "X" at 12495.02,1699.64 h60
  text "RoHS" at 12631.96,1699.64 h60
  text "OTHER" at 13276.36,1699.64 h60
  text "PER ORDER" at 13673.42,1699.64 h60
  text "ALL BOARDS MUST MEET OR EXCEED UL94-V0 REQUIREMENTS." at 11357,1534 h60
  text "PCB MUST BEAR THE UL94V-0 UL REGISTERED MATERIAL ID NUMBER" at 11357,1414 h60
  text "ADDITIONAL REQUIREMENTS:" at 11329.46,1240.64 h60
  text "MICROSECTION:" at 11404.23,1125.64 h60
  text "YES" at 12309.96,1125.64 h60
  text "REQUIRED" at 13171.46,969.49 h60
  text "BARE BOARD ELEC. TEST:" at 11404.23,966.64 h60
  text "NONE" at 12709.96,966.64 h60
  text "X" at 13044.46,966.64 h60
  text "PER ORDER" at 13763.46,966.64 h60
  text ".Layer_Name" at 577,-858.49 h60
M11 Gerber Information:
  lines w10: -292,-930.17 6308,-930.17 ; -292,-726.83 6310,-726.83 ; -292,-523.5 -292,-1133.5 3713,-1133.5 6310,-1133.5 6310,-523.5 -291.5,-523.5 -291.5,-1133.5 1284,-1133.5 ; 2173,-1133.5 2173,-523.5 ; 3440,-726.83 3440,-523.5 ; 4280,-726.83 4280,-523.5 ; 4902,-1140 4902,-937.17
  text "ALL ARTWORK VIEWED FROM TOP SIDE" at -228.5,-655.67 h60
  text "BOARD #:" at 2248,-655.67 h60
  text ".PRJ_Number" at 2793.5,-655.67 h60
  text "REV:" at 3638,-655.67 h60
  text ".PCB_Rev" at 3929.5,-655.67 h60
  text "SVN REV:" at 4476,-655.67 h60
  text ".VersionControl_RevNumber" at 4982,-655.67 h60
  text "LAYER NAME =" at -228.5,-858.49 h60
  text "TID #:" at 2248,-859 h60
  text ".TID" at 2793.5,-859 h60
  text "PLOT NAME =" at -228.5,-1064.34 h60
  text ".plot_File_Name" at 577,-1064.34 h60
  text "GENERATED    :" at 2250,-1064.34 h60
  text ".Print_Date" at 3119.5,-1064.34 h60
  text ".Print_Time" at 3848.5,-1064.34 h60
  text "TEXAS INSTRUMENTS" at 5113,-1064.34 h60
M12 Stackup:
  drawing of 191 lines, arcs and shapes, not listed
  text "Layer" at 9790.34,7830 h60
  text "Name" at 10200.26,7830 h60
  text "Material" at 11130,7830 h60
  text "Thickness" at 11989.77,7830 h60
  text "Constant" at 12639.6,7830 h60
  text "Board Layer Stack" at 13209.46,7830 h60
  text "1" at 9790.34,7710 h60
  text "Top Overlay" at 10200.26,7710 h60
  text "2" at 9790.34,7590 h60
  text "Top Solder" at 10200.26,7590 h60
  text "Solder Resist" at 11130,7590 h60
  text "0.40mil" at 11989.77,7590 h60
  text "3.5" at 12639.6,7590 h60
  text "3" at 9790.34,7470 h60
  text "Top Layer" at 10200.26,7470 h60
  text "Copper" at 11130,7470 h60
  text "1.40mil" at 11989.77,7470 h60
  text "4" at 9790.34,7350 h60
  text "Dielectric1" at 10200.26,7350 h60
  text "FR-4" at 11130,7350 h60
  text "59.20mil" at 11989.77,7350 h60
  text "4.8" at 12639.6,7350 h60
  text "5" at 9790.34,7230 h60
  text "Bottom Layer" at 10200.26,7230 h60
  text "Copper" at 11130,7230 h60
  text "1.40mil" at 11989.77,7230 h60
  text "6" at 9790.34,7110 h60
  text "Bottom Solder" at 10200.26,7110 h60
  text "Solder Resist" at 11130,7110 h60
  text "0.40mil" at 11989.77,7110 h60
  text "3.5" at 12639.6,7110 h60
  text "7" at 9790.34,6990 h60
  text "Bottom Overlay" at 10200.26,6990 h60
  text ".Layer_Name" at 577,-858.49 h60
M13 Component Bodies Top:
  text ".Layer_Name" at 577,-858.49 h60
M14 Component Bodies Bottom:
  text ".Layer_Name" at 577,-858.49 h60
M15 Courtyards Top:
  text ".Layer_Name" at 577,-858.49 h60
M16 Courtyards Bottom:
  text ".Layer_Name" at 577,-858.49 h60
Drill Drawing:
  drawing of 183 lines, arcs and shapes, not listed
  text "Symbol" at 5360.59,3368.3 h72
  text "Quantity" at 5661.16,3368.3 h72
  text "Finished Hole Size" at 5993.16,3368.3 h72
  text "Plated" at 6629.72,3368.3 h72
  text "Hole Type" at 6888.86,3368.3 h72
  text "Drill Layer Pair" at 7264.02,3368.3 h72
  text "Hole Tolerance" at 7988.35,3368.3 h72
  text "2" at 5661.16,3243.98 h60
  text "77.95mil (1.980mm)" at 5993.16,3243.98 h60
  text "NPTH" at 6629.72,3243.98 h60
  text "Round" at 6888.86,3243.98 h60
  text "Top Layer - Bottom Layer" at 7264.02,3243.98 h60
  text "5" at 5661.16,3119.66 h60
  text "7.87mil (0.200mm)" at 5993.16,3119.66 h60
  text "PTH" at 6629.72,3119.66 h60
  text "Round" at 6888.86,3119.66 h60
  text "Top Layer - Bottom Layer" at 7264.02,3119.66 h60
  text "4" at 5661.16,2995.34 h60
  text "17.72mil (0.450mm)" at 5993.16,2995.34 h60
  text "PTH" at 6629.72,2995.34 h60
  text "Round" at 6888.86,2995.34 h60
  text "Top Layer - Bottom Layer" at 7264.02,2995.34 h60
  text "24" at 5661.16,2871.02 h60
  text "19.69mil (0.500mm)" at 5993.16,2871.02 h60
  text "PTH" at 6629.72,2871.02 h60
  text "Round" at 6888.86,2871.02 h60
  text "Top Layer - Bottom Layer" at 7264.02,2871.02 h60
  text "94" at 5661.16,2746.7 h60
  text "28.00mil (0.711mm)" at 5993.16,2746.7 h60
  text "PTH" at 6629.72,2746.7 h60
  text "Round" at 6888.86,2746.7 h60
  text "Top Layer - Bottom Layer" at 7264.02,2746.7 h60
  text "A" at 5335.31,2736.71 h55.25
  text "38" at 5661.16,2622.38 h60
  text "30.00mil (0.762mm)" at 5993.16,2622.38 h60
  text "PTH" at 6629.72,2622.38 h60
  text "Round" at 6888.86,2622.38 h60
  text "Top Layer - Bottom Layer" at 7264.02,2622.38 h60
  text "3" at 5661.16,2498.06 h60
  text "31.50mil (0.800mm)" at 5993.16,2498.06 h60
  text "PTH" at 6629.72,2498.06 h60
  text "Round" at 6888.86,2498.06 h60
  text "Top Layer - Bottom Layer" at 7264.02,2498.06 h60
  text "2" at 5661.16,2373.74 h60
  text "33.46mil (0.850mm)" at 5993.16,2373.74 h60
  text "PTH" at 6629.72,2373.74 h60
  text "Round" at 6888.86,2373.74 h60
  text "Top Layer - Bottom Layer" at 7264.02,2373.74 h60
  text "12" at 5661.16,2249.42 h60
  text "39.37mil (1.000mm)" at 5993.16,2249.42 h60
  text "PTH" at 6629.72,2249.42 h60
  text "Round" at 6888.86,2249.42 h60
  text "Top Layer - Bottom Layer" at 7264.02,2249.42 h60
  text "4" at 5661.16,2125.1 h60
  text "46.85mil (1.190mm)" at 5993.16,2125.1 h60
  text "PTH" at 6629.72,2125.1 h60
  text "Round" at 6888.86,2125.1 h60
  text "Top Layer - Bottom Layer" at 7264.02,2125.1 h60
  text "14" at 5661.16,2000.78 h60
  text "47.24mil (1.200mm)" at 5993.16,2000.78 h60
  text "PTH" at 6629.72,2000.78 h60
  text "Round" at 6888.86,2000.78 h60
  text "Top Layer - Bottom Layer" at 7264.02,2000.78 h60
  text "3" at 5661.16,1876.46 h60
  text "59.06mil (1.500mm)" at 5993.16,1876.46 h60
  text "PTH" at 6629.72,1876.46 h60
  text "Round" at 6888.86,1876.46 h60
  text "Top Layer - Bottom Layer" at 7264.02,1876.46 h60
  text "3" at 5661.16,1752.14 h60
  text "100.00mil (2.540mm)" at 5993.16,1752.14 h60
  text "PTH" at 6629.72,1752.14 h60
  text "Round" at 6888.86,1752.14 h60
  text "Top Layer - Bottom Layer" at 7264.02,1752.14 h60
  text "4" at 5661.16,1627.82 h60
  text "129.92mil (3.300mm)" at 5993.16,1627.82 h60
  text "PTH" at 6629.72,1627.82 h60
  text "Round" at 6888.86,1627.82 h60
  text "Top Layer - Bottom Layer" at 7264.02,1627.82 h60
  text "2" at 5661.16,1503.5 h60
  text "23.62mil (0.600mm)" at 5993.16,1503.5 h60
  text "PTH" at 6629.72,1503.5 h60
  text "Slot" at 6888.86,1503.5 h60
  text "Top Layer - Bottom Layer" at 7264.02,1503.5 h60
  text "214 Total" at 5661.16,1379.18 h60
  text "Slot definitions :" at 5360.59,1292.15 h60
  text "Routed Path Length" at 5811.31,1292.15 h60
  text "= Calculated from tool start centre position to tool end centre position." at 6351.05,1292.15 h60
  text "Hole Length" at 5811.31,1242.43 h60
  text "= Routed Path Length + Tool Size = Slot length as defined in the PCB layout" at 6151.24,1242.43 h60
  text ".Layer_Name" at 577,-858.49 h60
M17 Embedded Cavity:
  text ".Layer_Name" at 577,-858.49 h60
M18 Embedded Assembly:
  text ".Layer_Name" at 577,-858.49 h60
M19 Embedded Keepout:
  text ".Layer_Name" at 577,-858.49 h60

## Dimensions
0,-400 to 1000,-400 on M2 Board Dimensions
3020,4285 to 40,4285 on M2 Board Dimensions
40,4285 to 3020,4285 on M2 Board Dimensions
25,4260 to 25,30 on M2 Board Dimensions
25,35 to 25,4260 on M2 Board Dimensions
